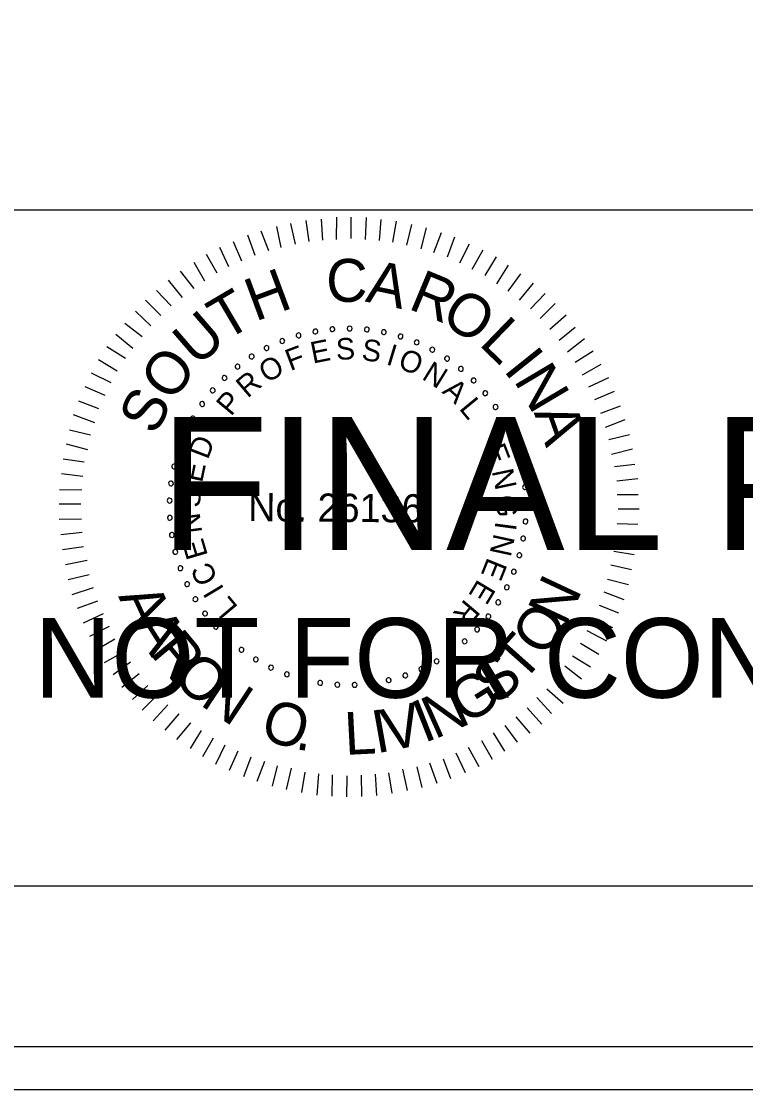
# Model space of a CAD drawing. Extents: x 967 to 1326, y 964 to 3144.
# Drawn here: x 1170.56 to 1189.3, y 2643.72 to 2671.36 of the extents above; entities that cross this region are included whole.
import ezdxf

# ---------------------------------------------------------------- set-up
doc = ezdxf.new("R2010")
doc.units = 0
for name, color, linetype in [('RD_XS_EwShp', 7, 'Continuous'), ('RD_XS_ExPaveRet', 7, 'Continuous'), ('RD_XS_TX_Elev_EX', 7, 'Continuous'), ('RD_XS_TX_Elev_PR', 7, 'Continuous'), ('RD_XS_TX_Station', 7, 'Continuous')]:
    doc.layers.add(name, color=color, linetype=linetype)

msp = doc.modelspace()

# ---------------------------------------------------------------- linework, layer by layer
at = {"layer": 'RD_XS_ExPaveRet'}
for points in [[(967.409, 2643.72), (1326.285, 2643.72), (1326.285, 2863.72), (967.409, 2863.72)], [(988.525, 2644.84), (1326.285, 2644.84), (1326.285, 2862.6), (988.525, 2862.6)]]:
    msp.add_lwpolyline(points, close=True, dxfattribs=at)
at = {"layer": 'RD_XS_TX_Elev_EX'}
for p, q in [((996.114, 2666.486), (1323.886, 2666.486)), ((1323.886, 2648.983), (996.114, 2648.983))]:
    msp.add_line(p, q, dxfattribs=at)
at = {"layer": 'RD_XS_TX_Elev_PR'}
for p, q in [((1178.01, 2665.663), (1177.93, 2666.209)), ((1178.364, 2665.699), (1178.33, 2666.244)), ((1178.717, 2665.719), (1178.722, 2666.295)), ((1179.093, 2665.739), (1179.098, 2666.292)), ((1179.469, 2665.713), (1179.489, 2666.288)), ((1179.829, 2665.687), (1179.872, 2666.231)), ((1180.174, 2665.646), (1180.271, 2666.19)), ((1176.964, 2665.419), (1176.769, 2665.935)), ((1177.287, 2665.508), (1177.169, 2666.054)), ((1177.657, 2665.597), (1177.53, 2666.128)), ((1180.535, 2665.573), (1180.662, 2666.102)), ((1180.902, 2665.478), (1181.045, 2666.022)), ((1181.231, 2665.384), (1181.428, 2665.896)), ((1176.264, 2665.156), (1176.053, 2665.657)), ((1176.61, 2665.306), (1176.423, 2665.83)), ((1181.584, 2665.265), (1181.78, 2665.786)), ((1181.905, 2665.109), (1182.154, 2665.606)), ((1175.624, 2664.846), (1175.352, 2665.332)), ((1175.933, 2665.005), (1175.699, 2665.506)), ((1182.226, 2664.953), (1182.506, 2665.45)), ((1175.308, 2664.634), (1175.036, 2665.12)), ((1182.562, 2664.789), (1182.85, 2665.27)), ((1182.86, 2664.572), (1183.163, 2665.053)), ((1175.03, 2664.445), (1174.681, 2664.9)), ((1183.158, 2664.378), (1183.484, 2664.828)), ((1174.729, 2664.217), (1174.372, 2664.665)), ((1183.447, 2664.145), (1183.811, 2664.587)), ((1174.435, 2663.997), (1174.062, 2664.399)), ((1183.729, 2663.92), (1184.116, 2664.316)), ((1174.172, 2663.753), (1173.776, 2664.148)), ((1183.98, 2663.672), (1184.368, 2664.061)), ((1173.909, 2663.479), (1173.52, 2663.858)), ((1184.232, 2663.394), (1184.657, 2663.767)), ((1173.684, 2663.197), (1173.242, 2663.546)), ((1184.475, 2663.108), (1184.892, 2663.45)), ((1173.451, 2662.9), (1173.009, 2663.256)), ((1184.687, 2662.807), (1185.128, 2663.156)), ((1173.257, 2662.64), (1172.776, 2662.936)), ((1184.885, 2662.544), (1185.355, 2662.832)), ((1173.039, 2662.312), (1172.559, 2662.6)), ((1185.081, 2662.213), (1185.56, 2662.493)), ((1172.883, 2662.006), (1172.379, 2662.256)), ((1185.24, 2661.904), (1185.756, 2662.145)), ((1172.727, 2661.677), (1172.215, 2661.904)), ((1185.399, 2661.573), (1185.907, 2661.791)), ((1172.571, 2661.333), (1172.051, 2661.53)), ((1172.461, 2660.974), (1171.91, 2661.178)), ((1185.549, 2661.226), (1186.057, 2661.414)), ((1185.669, 2660.865), (1186.185, 2661.06)), ((1172.351, 2660.652), (1171.807, 2660.787)), ((1185.759, 2660.541), (1186.297, 2660.667)), ((1172.286, 2660.276), (1171.727, 2660.419)), ((1185.832, 2660.165), (1186.371, 2660.298)), ((1172.191, 2659.955), (1171.647, 2660.029)), ((1185.906, 2659.842), (1186.436, 2659.906)), ((1172.15, 2659.587), (1171.598, 2659.653)), ((1185.964, 2659.473), (1186.51, 2659.53)), ((1172.124, 2659.234), (1171.548, 2659.239)), ((1185.977, 2659.12), (1186.514, 2659.115)), ((1172.105, 2658.866), (1171.545, 2658.871)), ((1185.997, 2658.751), (1186.542, 2658.747)), ((1172.118, 2658.482), (1171.542, 2658.471)), ((1172.138, 2658.136), (1171.585, 2658.072)), ((1185.971, 2658.368), (1186.508, 2658.348)), ((1185.952, 2658.022), (1186.497, 2657.949)), ((1172.173, 2657.768), (1171.627, 2657.688)), ((1185.888, 2657.655), (1186.417, 2657.566)), ((1172.262, 2657.414), (1171.701, 2657.296)), ((1185.808, 2657.302), (1186.345, 2657.175)), ((1172.321, 2657.037), (1171.774, 2656.911)), ((1185.729, 2656.926), (1186.265, 2656.792)), ((1172.425, 2656.707), (1171.871, 2656.519)), ((1185.634, 2656.597), (1186.146, 2656.401)), ((1172.53, 2656.36), (1172.007, 2656.173)), ((1185.508, 2656.253), (1186.013, 2656.057)), ((1172.681, 2656.029), (1172.165, 2655.788)), ((1185.352, 2655.924), (1185.857, 2655.675)), ((1172.831, 2655.705), (1172.323, 2655.441)), ((1172.982, 2655.374), (1172.497, 2655.094)), ((1185.188, 2655.603), (1185.7, 2655.33)), ((1185.024, 2655.274), (1185.498, 2654.987)), ((1173.194, 2655.042), (1172.709, 2654.762)), ((1184.822, 2654.946), (1185.288, 2654.658)), ((1173.384, 2654.78), (1172.936, 2654.453)), ((1184.62, 2654.687), (1185.055, 2654.353)), ((1173.612, 2654.478), (1173.164, 2654.129)), ((1184.403, 2654.389), (1184.814, 2654.033)), ((1173.832, 2654.177), (1173.437, 2653.812)), ((1184.155, 2654.092), (1184.574, 2653.72)), ((1174.091, 2653.945), (1173.689, 2653.541)), ((1183.899, 2653.864), (1184.28, 2653.454)), ((1174.35, 2653.674), (1173.97, 2653.263)), ((1174.64, 2653.442), (1174.275, 2653.022)), ((1183.644, 2653.597), (1184.024, 2653.18)), ((1174.937, 2653.209), (1174.58, 2652.782)), ((1183.065, 2653.141), (1183.384, 2652.709)), ((1183.358, 2653.37), (1183.715, 2652.944)), ((1175.212, 2653.014), (1174.932, 2652.549)), ((1182.764, 2652.952), (1183.059, 2652.482)), ((1175.525, 2652.812), (1175.245, 2652.331)), ((1175.83, 2652.633), (1175.588, 2652.136)), ((1182.463, 2652.755), (1182.743, 2652.269)), ((1176.159, 2652.477), (1175.94, 2651.98)), ((1176.503, 2652.321), (1176.307, 2651.816)), ((1181.8, 2652.431), (1182.041, 2651.93)), ((1182.124, 2652.581), (1182.396, 2652.08)), ((1176.855, 2652.211), (1176.651, 2651.69)), ((1177.177, 2652.1), (1177.05, 2651.572)), ((1177.545, 2652.036), (1177.409, 2651.484)), ((1180.791, 2652.07), (1180.926, 2651.54)), ((1181.122, 2652.175), (1181.31, 2651.652)), ((1181.476, 2652.28), (1181.664, 2651.771)), ((1177.897, 2651.933), (1177.808, 2651.412)), ((1178.25, 2651.892), (1178.207, 2651.34)), ((1178.603, 2651.866), (1178.598, 2651.313)), ((1178.978, 2651.84), (1178.974, 2651.295)), ((1179.355, 2651.86), (1179.365, 2651.307)), ((1179.715, 2651.88), (1179.749, 2651.327)), ((1180.061, 2651.915), (1180.149, 2651.393)), ((1180.423, 2652.012), (1180.541, 2651.458))]:
    msp.add_line(p, q, dxfattribs=at)
for centre, start, end in [((1178.168, 2663.337), 10.6038, 190.6038), ((1178.609, 2663.397), 5.0653, 185.0653), ((1178.609, 2663.397), 185.0653, 5.0653), ((1179.055, 2663.414), 359.5268, 179.5268), ((1179.055, 2663.414), 179.5268, 359.5268), ((1179.5, 2663.388), 353.9884, 173.9884), ((1179.5, 2663.388), 173.9884, 353.9884), ((1179.94, 2663.319), 348.4499, 168.4499), ((1177.312, 2663.091), 21.6807, 201.6807), ((1177.312, 2663.091), 201.6807, 21.6807), ((1177.734, 2663.235), 16.1422, 196.1422), ((1177.734, 2663.235), 196.1422, 16.1422), ((1178.168, 2663.337), 190.6038, 10.6038), ((1179.94, 2663.319), 168.4499, 348.4499), ((1180.372, 2663.208), 162.9114, 342.9114), ((1180.372, 2663.208), 342.9114, 162.9114), ((1180.79, 2663.056), 337.373, 157.373), ((1176.906, 2662.908), 27.2191, 207.2191), ((1176.906, 2662.908), 207.2191, 27.2191), ((1180.79, 2663.056), 157.373, 337.373), ((1181.193, 2662.864), 151.8345, 331.8345), ((1181.193, 2662.864), 331.8345, 151.8345), ((1176.52, 2662.686), 32.7576, 212.7576), ((1176.52, 2662.686), 212.7576, 32.7576), ((1181.574, 2662.634), 146.2961, 326.2961), ((1181.574, 2662.634), 326.2961, 146.2961), ((1176.156, 2662.428), 38.2961, 218.2961), ((1176.156, 2662.428), 218.2961, 38.2961), ((1181.932, 2662.368), 140.7576, 320.7576), ((1181.932, 2662.368), 320.7576, 140.7576), ((1175.82, 2662.135), 43.8345, 223.8345), ((1175.82, 2662.135), 223.8345, 43.8345), ((1182.263, 2662.069), 135.2191, 315.2191), ((1182.263, 2662.069), 315.2191, 135.2191), ((1175.513, 2661.812), 49.373, 229.373), ((1175.513, 2661.812), 229.373, 49.373), ((1182.563, 2661.74), 129.6807, 309.6807), ((1182.563, 2661.74), 309.6807, 129.6807), ((1175.239, 2661.461), 54.9114, 234.9114), ((1175.239, 2661.461), 234.9114, 54.9114), ((1182.83, 2661.383), 124.1422, 304.1422), ((1182.83, 2661.383), 304.1422, 124.1422), ((1175, 2661.085), 60.4499, 240.4499), ((1175, 2661.085), 240.4499, 60.4499), ((1183.061, 2661.002), 118.6038, 298.6038), ((1183.061, 2661.002), 298.6038, 118.6038), ((1174.798, 2660.687), 65.9884, 245.9884), ((1174.798, 2660.687), 245.9884, 65.9884), ((1183.255, 2660.601), 113.0653, 293.0653), ((1183.255, 2660.601), 293.0653, 113.0653), ((1174.636, 2660.272), 71.5268, 251.5268), ((1174.636, 2660.272), 251.5268, 71.5268), ((1183.408, 2660.182), 107.5268, 287.5268), ((1183.408, 2660.182), 287.5268, 107.5268), ((1174.514, 2659.843), 77.0653, 257.0653), ((1174.514, 2659.843), 257.0653, 77.0653), ((1183.521, 2659.751), 101.9884, 281.9884), ((1183.521, 2659.751), 281.9884, 101.9884), ((1174.435, 2659.405), 82.6038, 262.6038), ((1174.435, 2659.405), 262.6038, 82.6038), ((1183.592, 2659.311), 96.4499, 276.4499), ((1183.592, 2659.311), 276.4499, 96.4499), ((1174.398, 2658.961), 88.1422, 268.1422), ((1174.398, 2658.961), 268.1422, 88.1422), ((1183.619, 2658.866), 90.9114, 270.9114), ((1183.619, 2658.866), 270.9114, 90.9114), ((1174.404, 2658.515), 93.6807, 273.6807), ((1174.404, 2658.515), 273.6807, 93.6807), ((1183.604, 2658.421), 85.373, 265.373), ((1183.604, 2658.421), 265.373, 85.373), ((1174.453, 2658.072), 99.2191, 279.2191), ((1174.453, 2658.072), 279.2191, 99.2191), ((1183.546, 2657.979), 79.8345, 259.8345), ((1183.546, 2657.979), 259.8345, 79.8345), ((1174.545, 2657.636), 104.7576, 284.7576), ((1174.545, 2657.636), 284.7576, 104.7576), ((1183.445, 2657.545), 74.2961, 254.2961), ((1183.445, 2657.545), 254.2961, 74.2961), ((1174.678, 2657.211), 110.2961, 290.2961), ((1174.678, 2657.211), 290.2961, 110.2961), ((1183.303, 2657.122), 68.7576, 248.7576), ((1183.303, 2657.122), 248.7576, 68.7576), ((1174.852, 2656.8), 115.8345, 295.8345), ((1174.852, 2656.8), 295.8345, 115.8345), ((1183.121, 2656.716), 63.2191, 243.2191), ((1183.121, 2656.716), 243.2191, 63.2191), ((1175.065, 2656.409), 121.373, 301.373), ((1175.065, 2656.409), 301.373, 121.373), ((1182.9, 2656.328), 57.6807, 237.6807), ((1182.9, 2656.328), 237.6807, 57.6807), ((1175.314, 2656.039), 126.9114, 306.9114), ((1175.314, 2656.039), 306.9114, 126.9114), ((1182.643, 2655.964), 52.1422, 232.1422), ((1182.643, 2655.964), 232.1422, 52.1422), ((1175.598, 2655.696), 132.4499, 312.4499), ((1175.598, 2655.696), 312.4499, 132.4499), ((1182.353, 2655.627), 46.6038, 226.6038), ((1182.353, 2655.627), 226.6038, 46.6038), ((1175.914, 2655.381), 137.9884, 317.9884), ((1175.914, 2655.381), 317.9884, 137.9884), ((1182.03, 2655.319), 41.0653, 221.0653), ((1182.03, 2655.319), 221.0653, 41.0653), ((1176.258, 2655.099), 143.5268, 323.5268), ((1176.258, 2655.099), 323.5268, 143.5268), ((1181.68, 2655.043), 35.5268, 215.5268), ((1181.68, 2655.043), 215.5268, 35.5268), ((1176.629, 2654.851), 149.0653, 329.0653), ((1176.629, 2654.851), 329.0653, 149.0653), ((1181.305, 2654.803), 29.9884, 209.9884), ((1181.305, 2654.803), 209.9884, 29.9884), ((1177.021, 2654.639), 154.6038, 334.6038), ((1177.021, 2654.639), 334.6038, 154.6038), ((1177.432, 2654.467), 340.1422, 160.1422), ((1180.908, 2654.6), 24.4499, 204.4499), ((1180.908, 2654.6), 204.4499, 24.4499), ((1177.432, 2654.467), 160.1422, 340.1422), ((1177.858, 2654.335), 165.6807, 345.6807), ((1177.858, 2654.335), 345.6807, 165.6807), ((1178.294, 2654.245), 351.2191, 171.2191), ((1178.294, 2654.245), 171.2191, 351.2191), ((1178.737, 2654.198), 356.7576, 176.7576), ((1179.183, 2654.193), 2.2961, 182.2961), ((1179.627, 2654.232), 7.8345, 187.8345), ((1180.065, 2654.313), 13.373, 193.373), ((1180.065, 2654.313), 193.373, 13.373), ((1180.494, 2654.436), 18.9114, 198.9114), ((1180.494, 2654.436), 198.9114, 18.9114), ((1178.737, 2654.198), 176.7576, 356.7576), ((1179.183, 2654.193), 182.2961, 2.2961), ((1179.627, 2654.232), 187.8345, 7.8345)]:
    msp.add_arc(centre, 0.0627, start, end, dxfattribs=at)
at = {"layer": 'RD_XS_TX_Station'}
msp.add_lwpolyline([(967.409, 2643.72), (1326.285, 2643.72), (1326.285, 2863.72), (967.409, 2863.72)], close=True, dxfattribs=at)

# ---------------------------------------------------------------- texts
at = {"layer": 'RD_XS_EwShp'}
for s, height, p in [('FINAL PLANS', 3.4375, (1174.145, 2657.685)), ('NOT FOR CONSTRUCTION', 2.0625, (1170.901, 2653.86))]:
    msp.add_text(s, height=height, dxfattribs=at).set_placement(p)
at = {"layer": 'RD_XS_TX_Elev_PR'}
for s, height, rotation, p in [('C', 1.11, 359.5482, (1178.442, 2664.108)), ('A', 1.11, 348.1981, (1179.439, 2664.115)), ('H', 1.11, 20.3637, (1176.614, 2663.587)), ('R', 1.11, 337.4344, (1180.541, 2663.937)), ('T', 1.11, 30.4992, (1175.828, 2663.072)), ('O', 1.108, 326.5869, (1181.366, 2663.609)), ('U', 1.11, 40.8022, (1175.102, 2662.403)), ('L', 1.11, 315.9488, (1182.373, 2663.003)), ('E', 0.557, 11.4103, (1178.103, 2662.503)), ('S', 0.557, 2.208, (1178.709, 2662.601)), ('S', 0.557, 352.6608, (1179.346, 2662.599)), ('O', 1.11, 52.0267, (1174.435, 2661.474)), ('F', 0.557, 20.6127, (1177.52, 2662.309)), ('I', 0.557, 343.1136, (1179.975, 2662.491)), ('O', 0.557, 338.4392, (1180.274, 2662.401)), ('I', 1.11, 308.6613, (1183.011, 2662.338)), ('O', 0.557, 30.8477, (1176.917, 2661.987)), ('N', 0.557, 328.2042, (1180.896, 2662.12)), ('R', 0.557, 40.3949, (1176.415, 2661.594)), ('N', 1.11, 300.7037, (1183.285, 2662.075)), ('A', 0.557, 318.657, (1181.424, 2661.762)), ('S', 1.108, 63.2511, (1174.029, 2660.619)), ('P', 0.557, 49.9421, (1175.985, 2661.124)), ('L', 0.557, 309.4546, (1181.869, 2661.339)), ('A', 1.11, 289.4792, (1183.814, 2661.243)), ('D', 0.557, 69.0364, (1175.386, 2660.003)), ('E', 0.557, 291.049, (1182.53, 2660.307)), ('E', 0.557, 78.2388, (1175.238, 2659.407)), ('N', 0.557, 281.8466, (1182.728, 2659.726)), ('S', 0.557, 87.786, (1175.187, 2658.772)), ('No. 26136', 0.7311, 359.5268, (1176.429, 2658.43)), ('G', 0.557, 272.2995, (1182.833, 2659.097)), ('N', 0.557, 97.3332, (1175.242, 2658.137)), ('I', 0.557, 262.4084, (1182.83, 2658.437)), ('E', 0.557, 106.5355, (1175.394, 2657.541)), ('N', 0.557, 257.7339, (1182.789, 2658.127)), ('C', 0.557, 116.4266, (1175.661, 2656.938)), ('E', 0.557, 248.1867, (1182.628, 2657.511)), ('N', 1.105, 64.8922, (1184.632, 2655.684)), ('I', 0.557, 121.1011, (1175.823, 2656.67)), ('E', 0.557, 238.9844, (1182.378, 2656.949)), ('A', 1.105, 294.7297, (1173.062, 2656.486)), ('L', 0.557, 129.9595, (1176.187, 2656.204)), ('R', 0.557, 229.782, (1182.041, 2656.435)), ('O', 1.105, 56.2059, (1184.102, 2654.874)), ('A', 1.105, 302.2892, (1173.414, 2655.72)), ('R', 1.105, 309.8487, (1173.865, 2655.007)), ('T', 1.105, 48.2685, (1183.515, 2654.211)), ('O', 1.105, 317.7861, (1174.434, 2654.33)), ('S', 1.105, 40.3311, (1182.842, 2653.636)), ('N', 1.105, 326.4725, (1175.158, 2653.686)), ('G', 1.105, 32.0198, (1182.059, 2653.14)), ('N', 1.105, 24.0824, (1181.252, 2652.776)), ('O', 1.105, 342.3472, (1176.697, 2652.82)), ('V', 1.105, 12.7741, (1180.033, 2652.457)), ('I', 1.105, 21.4605, (1180.976, 2652.681)), ('L', 1.105, 2.9677, (1178.943, 2652.379)), ('I', 1.105, 10.1523, (1179.743, 2652.418)), ('.', 1.105, 351.0336, (1177.623, 2652.536))]:
    msp.add_text(s, height=height, rotation=rotation, dxfattribs=at).set_placement(p)

doc.saveas('drawing.dxf')
